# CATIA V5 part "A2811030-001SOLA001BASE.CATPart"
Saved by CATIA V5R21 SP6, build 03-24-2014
Part number: A2811030-001SOLA001BASE
Revision: --A
Definition: A2811030-001SOLA001.BASE
Source: made
Description: START_SOLV5_EF2000______
Property "PTC_WM_NAME": "A2811030-001SOLA001.BASE"
Property "PTC_WM_NUMBER": "A2811030-001SOLA001BASE"
Property "PTC_WM_REVISION": "--A"
Property "PTC_WM_INIT_REV": "01"
Bounding box of the stored display mesh (mm): x -28 to 202, y -28 to 28, z -5 to 80
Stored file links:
  J:\Transfer\Fueller Werkstudent\Stellungen\A2811030-001SOLA001BASE.CATPart
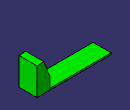
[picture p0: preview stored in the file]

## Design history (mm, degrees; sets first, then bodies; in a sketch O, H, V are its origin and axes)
AxisSystem1: origin (0, 0, 0), X (1, 0, 0), Y (0, 1, 0), Z (0, 0, 1)
Body1 (main body)
  Body2 "Positive"
    Sketch1 on xy-plane, origin (0, 0, 0), H (1, 0, 0), V (0, 1, 0)
      line L1 (-28, 28) -> (202, 28)
      line L2 (202, 28) -> (202, -28)
      line L3 (202, -28) -> (-28, -28)
      line L4 (-28, -28) -> (-28, 28)
      reference projected line E1 through (0, 0) direction (1, 0) from edge [XY plane of AxisSystem1 | ZX plane of AxisSystem1]
      reference projected line E2 through (0, 0) direction (0, 1) from edge [YZ plane of AxisSystem1 | XY plane of AxisSystem1]
      length L2 = 56
      distance L4 E2 = 28
      length L3 = 230
      horizontal: L1 H, L3 H
      vertical: L2 V, L4 V
      symmetry: L1 L3 E1
    Pad1: profile Sketch1, direction (0, 0, -1), length 5
    Sketch2 on ZX plane of AxisSystem1, origin (0, 0, 0), H (0, 0, 1), V (1, 0, 0)
      point P1 (0, 202)
      line L1 (0, 202) -> (80, 202)
      line L2 (80, 202) -> (80, 180)
      point P3 (80, 180)
      line L3 (80, 180) -> (30.5454, 162)
      line L4 (30.5454, 162) -> (0, 162)
      point P5 (0, 162)
      line L5 (0, 162) -> (0, 202)
      reference intersected line E1 (-5, 202) -> (0, 202) from face of Pad1 from Sketch1.L2
      length L1 = 80
      distance L4 L1 = 40
      angle L3 L2 = 110
      distance L1 P3 = 22
      coincidence: P1 V, P5 V, L1 E1
      horizontal: L1 H, L4 H
      vertical: L2 V, L5 V
    Pad2: profile Sketch2, direction (0, 1, 0), up to face of Pad1 from Sketch1.L1, opposite side up to face of Pad1 from Sketch1.L3
  Assemble1: tool Body2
